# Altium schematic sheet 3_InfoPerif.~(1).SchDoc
size 414 x 293 mm; SheetNumber: 3; SheetTotal: 4
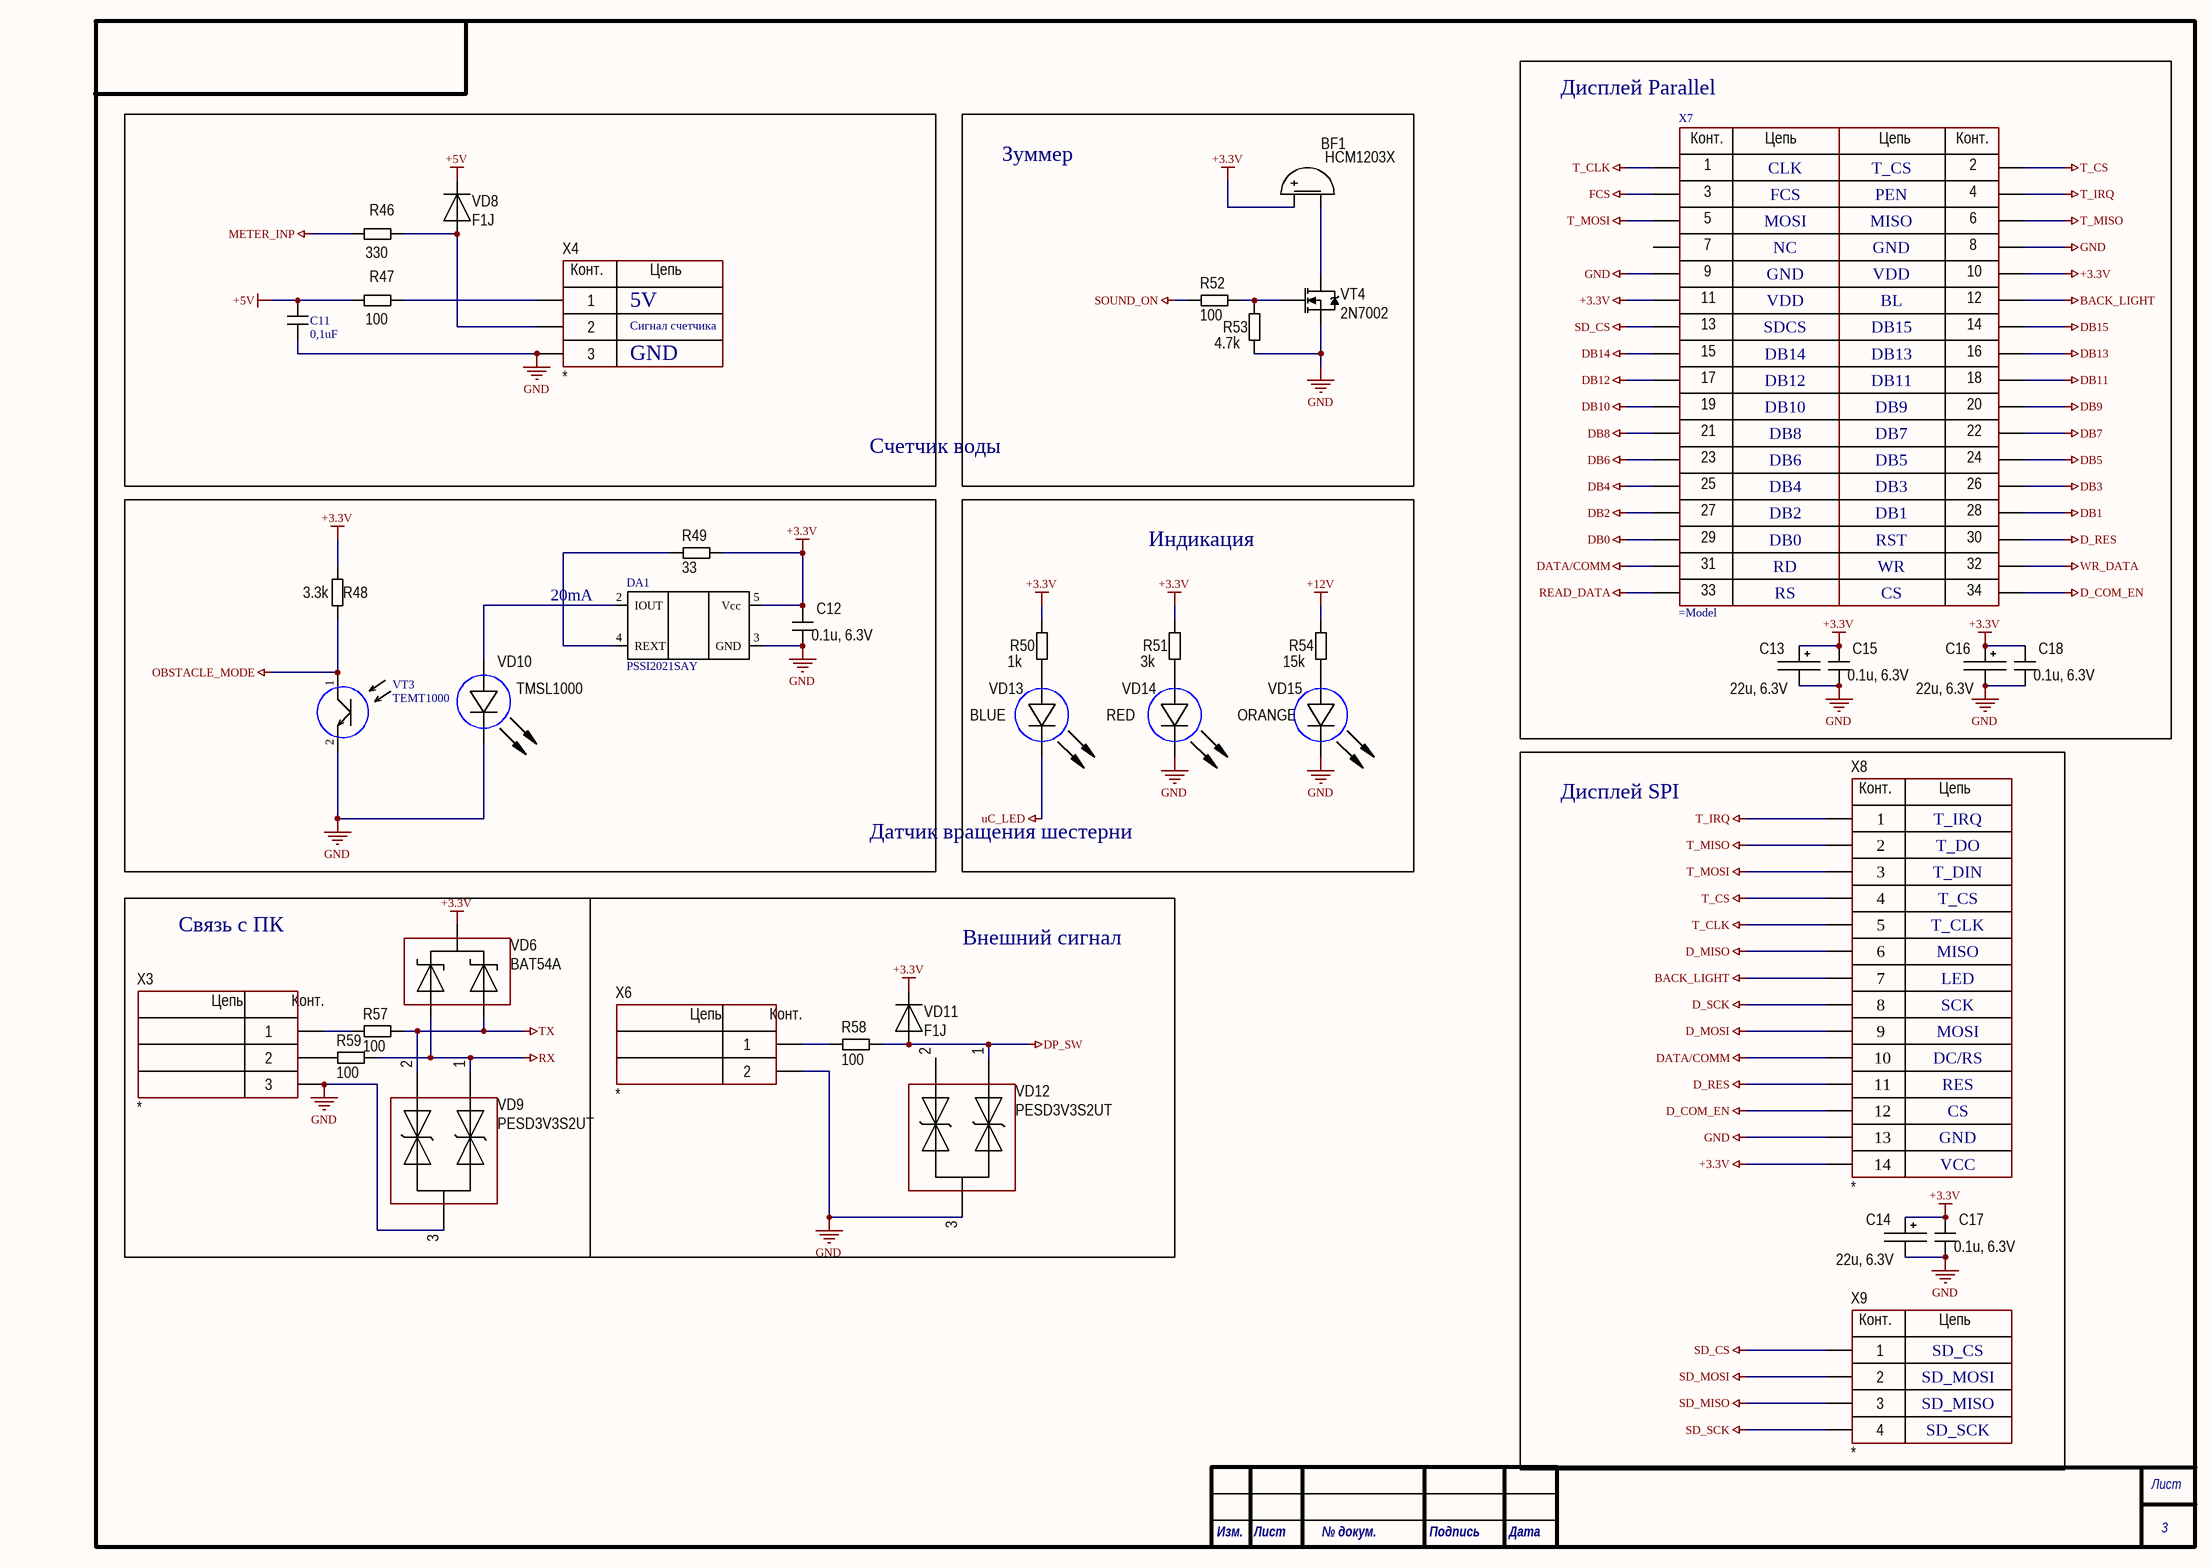
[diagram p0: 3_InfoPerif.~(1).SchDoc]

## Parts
BF1  HCM1203X  [BUZ: AI-1223-TWT-3V-2-R]
C11  0,1uF  [C_0603]
C12  0.1u, 6.3V  [CH0805C]
C13  22u, 6.3V  [TANTAL_B]
C14  22u, 6.3V  [TANTAL_B]
C15  0.1u, 6.3V  [CH0805C]
C16  22u, 6.3V  [TANTAL_B]
C17  0.1u, 6.3V  [CH0805C]
C18  0.1u, 6.3V  [CH0805C]
DA1  PSSI2021SAY  [SOT353]
R46  330  [CH0805R]
R47  100  [CH2512R]
R48  3.3k  [CH0805R]
R49  33  [CH0805R]
R50  1k  [CH0805R]
R51  3k  [CH0805R]
R52  100  [CH0805R]
R53  4.7k  [CH0805R]
R54  15k  [CH0805R]
R57  100  [CH0805R]
R58  100  [CH0805R]
R59  100  [CH0805R]
VD6  BAT54A  [SOT23_123]
VD8  F1J  [SOD123F]
VD9  PESD3V3S2UT  [SOT23_132]
VD10  TMSL1000  [TSML1000]
VD11  F1J  [SOD123F]
VD12  PESD3V3S2UT  [SOT23_132]
VD13  BLUE  [CH0603LB]
VD14  RED  [CH0603LB]
VD15  ORANGE  [CH0603LB]
VT3  TEMT1000  [TEMT1000]
VT4  2N7002  [SOT23_123]
X3  *  [CON: CWF-3]
X4  *  [CON: CWF-3]
X6  *  [CON: CWF-2]
X7  (no value)  [DS1023-34]
X8  *  [DS1024-14]
X9  *  [DS1023-4]

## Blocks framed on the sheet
Дисплей Parallel: C13 C15 C16 C18 X7
Зуммер: BF1 R52 R53 VT4
Датчик вращения шестерни: C12 DA1 R48 R49 VD10 VT3
Индикация: R50 R51 R54 VD13-VD15
Дисплей SPI: C14 C17 X8 X9
Связь с ПК: R57 R59 VD6 VD9 X3
Внешний сигнал: R58 VD11 VD12 X6

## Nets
+3.3V: BF1.1(+) C12.2 C13.1 C14.1 C15.2 C16.1 C17.2 C18.2 DA1.5(Vcc) R48.2 R49.2 R50.2 R51.2 VD6.2 VD11.2 X7.10 X7.11 X8.14
+5V: C11.2 R47.1 VD8.2
+12V: R54.2
BACK_LIGHT: X7.12 X8.7
D_COM_EN: X7.34 X8.12
D_MISO: X8.6
D_MOSI: X8.9
D_RES: X7.30 X8.11
D_SCK: X8.8
DATA/COMM: X7.31 X8.10
DB0: X7.29
DB1: X7.28
DB2: X7.27
DB3: X7.26
DB4: X7.25
DB5: X7.24
DB6: X7.23
DB7: X7.22
DB8: X7.21
DB9: X7.20
DB10: X7.19
DB11: X7.18
DB12: X7.17
DB13: X7.16
DB14: X7.15
DB15: X7.14
DP_SW: R58.2 VD11.1 VD12.1
FCS: X7.3
GND: C11.1 C12.1 C13.2 C14.2 C15.1 C16.2 C17.1 C18.1 DA1.3(GND) R53.1 VD9.3 VD10.2(C) VD12.3 VD14.2(C) VD15.2(C) VT3.2 VT4.3(S) X3.3 X4.3 X6.2 X7.8 X7.9 X8.13
METER_INP: R46.1
OBSTACLE_MODE: R48.1 VT3.1
READ_DATA: X7.33
RX: R59.2 VD6.3 VD9.1
SD_CS: X7.13 X9.1
SD_MISO: X9.3
SD_MOSI: X9.2
SD_SCK: X9.4
SOUND_ON: R52.2
T_CLK: X7.1 X8.5
T_CS: X7.2 X8.4
T_IRQ: X7.4 X8.1
T_MISO: X7.6 X8.2
T_MOSI: X7.5 X8.3
TX: R57.2 VD6.1 VD9.2
uC_LED: VD13.2(C)
WR_DATA: X7.32
NetBF1_2: BF1.2(-) VT4.2(D)
NetDA1_2: DA1.2(IOUT) VD10.1(A)
NetDA1_4: DA1.4(REXT) R49.1
NetR46_2: R46.2 VD8.1 X4.2
NetR47_2: R47.2 X4.1
NetR50_1: R50.1 VD13.1(A)
NetR51_1: R51.1 VD14.1(A)
NetR52_1: R52.1 R53.2 VT4.1(G)
NetR54_1: R54.1 VD15.1(A)
NetR57_1: R57.1 X3.1
NetR58_1: R58.1 X6.1
NetR59_1: R59.1 X3.2

Not connected (* = marked no-connect by the designer): VD12 2; X7 7

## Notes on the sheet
- (near X7) CLK
- (near X7) T_CS
- (near X7) FCS
- (near X7) MOSI
- (near X7) MISO
- (near X7) PEN
- 5V
- (near X7) NC
- (near X7) GND
- (near X7) VDD
- (near X7) BL
- GND
- Сигнал счетчика
- (near X7) SDCS
- (near X7) DB14
- (near X7) DB12
- (near X7) DB11
- (near X7) DB13
- (near X7) DB15
- (near X7) DB8
- (near X7) DB10
- (near X7) DB7
- (near X7) DB9
- Счетчик воды
- (near X7) DB2
- (near X7) DB4
- (near X7) DB6
- (near X7) DB1
- (near X7) DB3
- (near X7) DB5
- (near X7) DB0
- (near X7) RD
- (near X7) WR
- (near X7) RST
- 20mA
- (near X7) RS
- (near X7) CS
- T_IRQ
- T_DO
- T_DIN
- T_CS
- T_CLK
- MISO
- LED
- SCK
- MOSI
- DC/RS
- RES
- CS
- VCC
- SD_CS
- SD_MOSI
- SD_MISO
- SD_SCK

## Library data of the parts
BF1 = Buzzer: Manufacturer: PUI Audio, Inc.; Model: AI-1223-TWT-3V-2-R
C11 = C_SMD
C12 = Capacitor: 0805
C13 C14 C16 = TantalCap
C15 C17 C18 = Capacitor
DA1 = PSSI2021SAY: Iout = 0.617/Rext + 15 µA
R46 R47 R50-R54 R57-R59 = Resistor
R48 R49 = Resistor: 0805
VD6 = Diod Schottky Array v.1
VD8 VD11 = Diod
VD9 VD12 = TVS Array
VD10 VD13-VD15 = LED_1
VT4 = N-chanel: Mosfet
X3 X4 = 3-Connector
X6 = 2-Connector
X7 = 34-Connector
X8 = 14-Connector
X9 = 4-Connector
